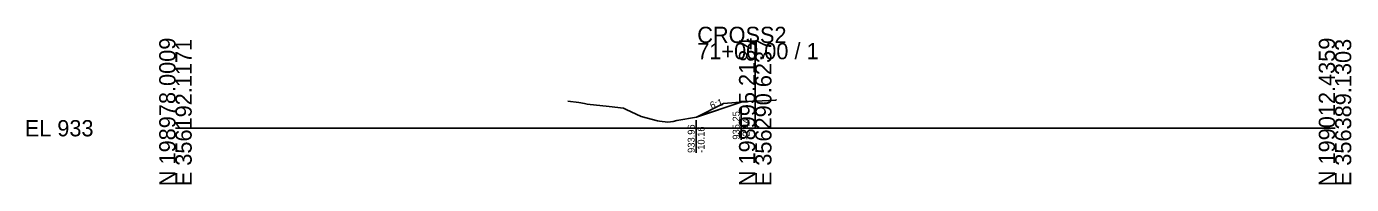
# Model space of a CAD drawing. Extents: x -26 to 203, y -10 to 14021.
# Drawn here: x -25.7 to 202.8, y 11990.3 to 12017.5 of the extents above; entities that cross this region are included whole.
import ezdxf

# ---------------------------------------------------------------- set-up
doc = ezdxf.new("R2010")
doc.units = 0
for name, color, linetype in [('Default', 7, 'Continuous'), ('P_E_XS_Ground', 7, 'Continuous'), ('P_XS', 7, 'Continuous'), ('P_XS_Lane', 7, 'Continuous'), ('P_XS_Rock', 7, 'Continuous')]:
    doc.layers.add(name, color=color, linetype=linetype)

msp = doc.modelspace()

# ---------------------------------------------------------------- linework, layer by layer
at = {"layer": 'Default'}
for p, q in [((100, 12000), (100, 12014.68)), ((0, 12000), (100, 12000)), ((100, 12000), (200, 12000))]:
    msp.add_line(p, q, dxfattribs=at)
at = {"layer": 'P_E_XS_Ground'}
for p, q in [((103.56, 12004.89), (103.65, 12004.89)), ((103.56, 12004.81), (103.56, 12004.89)), ((67.67, 12004.66), (69.59, 12004.44)), ((69.59, 12004.44), (70.55, 12004.23)), ((70.55, 12004.23), (70.99, 12004.15)), ((70.99, 12004.15), (74.78, 12003.73)), ((74.78, 12003.73), (77.25, 12003.45)), ((77.25, 12003.45), (77.74, 12003.21)), ((77.74, 12003.21), (80.35, 12001.99)), ((94.5, 12004.25), (89.84, 12001.92)), ((99.5, 12004.65), (94.5, 12004.25)), ((99.5, 12004.65), (100, 12004.67)), ((100, 12004.67), (103.56, 12004.81)), ((80.35, 12001.99), (83.14, 12001.25)), ((83.14, 12001.25), (83.46, 12001.2)), ((83.46, 12001.2), (84.95, 12001.07)), ((84.95, 12001.07), (85.84, 12001.14)), ((85.84, 12001.14), (86.45, 12001.31)), ((86.45, 12001.31), (89.84, 12001.92))]:
    msp.add_line(p, q, dxfattribs=at)
at = {"layer": 'P_XS'}
msp.add_line((91.56, 12002.49), (97.56, 12004.49), dxfattribs=at)
at = {"layer": 'P_XS_Lane'}
msp.add_line((89.84, 12001.92), (97.56, 12004.5), dxfattribs=at)
at = {"layer": 'P_XS_Rock'}
for p, q in [((97.56, 12003.62), (97.56, 11998.02)), ((89.81, 12001.37), (89.81, 11995.75))]:
    msp.add_line(p, q, dxfattribs=at)

# ---------------------------------------------------------------- texts
at = {"layer": 'Default'}
for s, p in [('CROSS2', (90, 12014.68)), ('71+00.00 / 1', (90, 12011.88)), ('EL 933', (-26, 11998.6))]:
    msp.add_text(s, height=2.8, dxfattribs=at).set_placement(p)
for s, p in [('N 198978.0009', (0, 11990)), ('E 356192.1171', (2.8, 11990)), ('N 198995.2184', (100, 11990)), ('E 356290.6237', (102.8, 11990)), ('N 199012.4359', (200, 11990)), ('E 356389.1303', (202.8, 11990))]:
    msp.add_text(s, height=2.8, rotation=90, dxfattribs=at).set_placement(p)
at = {"layer": 'P_XS_Rock'}
for s, rotation, p in [('6:1', 18.4349, (92.42, 12003.3)), ('935.25', 90, (97.31, 11998.03)), ('933.96', 90, (89.56, 11995.75)), ('-2.44', 90, (99.01, 11998.03)), ('-10.16', 90, (91.26, 11995.75))]:
    msp.add_text(s, height=1.2, rotation=rotation, dxfattribs=at).set_placement(p)

doc.saveas('drawing.dxf')
